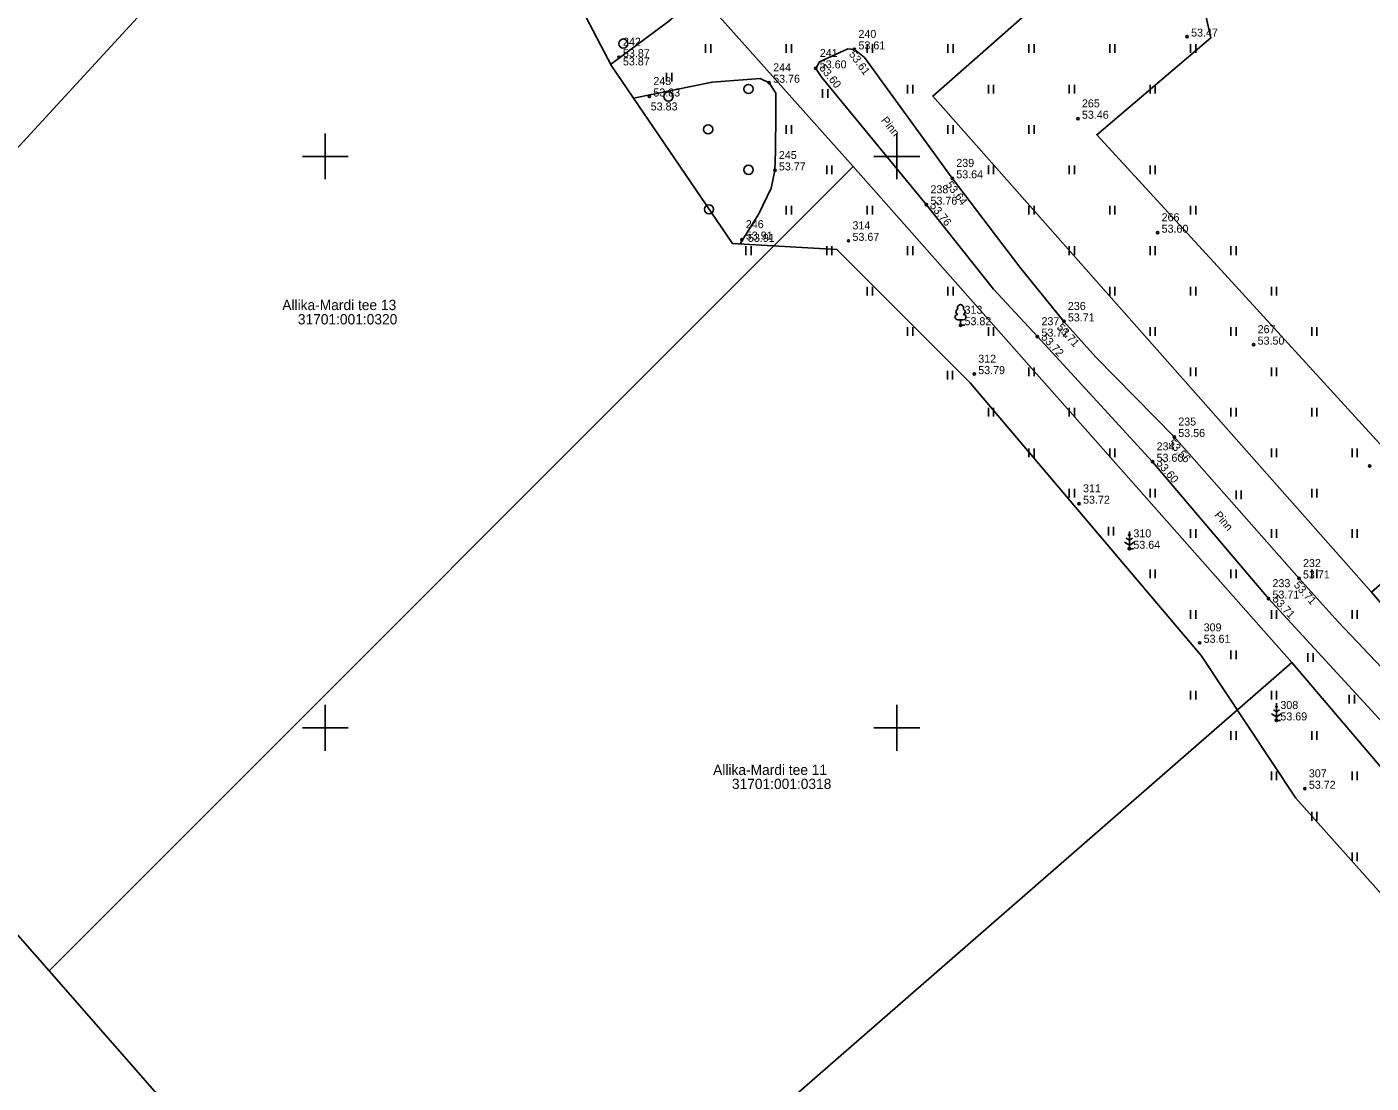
# Model space of a CAD drawing. Extents: x 538599 to 541973, y 6559689 to 6564516.
# Drawn here: x 540273.9 to 540391.5, y 6561418.9 to 6561511.3 of the extents above; entities that cross this region are included whole.
import ezdxf

# ---------------------------------------------------------------- set-up
doc = ezdxf.new("R2010")
doc.units = 0
for name, color, linetype in [('HALJASTUS', 7, 'Continuous'), ('KORGUS-EH2000', 7, 'Continuous'), ('MOOTKORG-EH2000', 7, 'Continuous'), ('MOOTMPUNKT', 7, 'Continuous'), ('MOOTNR', 7, 'Continuous'), ('MOOTPIIR', 7, 'Continuous'), ('PIIR', 7, 'Continuous'), ('PUU', 7, 'Continuous'), ('TEE', 7, 'Continuous'), ('VORK', 7, 'Continuous')]:
    doc.layers.add(name, color=color, linetype=linetype)

msp = doc.modelspace()

# ---------------------------------------------------------------- linework, layer by layer
at = {"layer": 'HALJASTUS'}
for p, q in [((540333.26, 6561509.81), (540333.26, 6561509.05)), ((540333.72, 6561509.81), (540333.72, 6561509.05)), ((540340.33, 6561509.81), (540340.33, 6561509.05)), ((540340.79, 6561509.81), (540340.79, 6561509.05)), ((540347.4, 6561509.81), (540347.4, 6561509.05)), ((540347.86, 6561509.81), (540347.86, 6561509.05)), ((540354.47, 6561509.81), (540354.47, 6561509.05)), ((540354.93, 6561509.81), (540354.93, 6561509.05)), ((540361.54, 6561509.81), (540361.54, 6561509.05)), ((540362, 6561509.81), (540362, 6561509.05)), ((540368.62, 6561509.81), (540368.62, 6561509.05)), ((540369.07, 6561509.81), (540369.07, 6561509.05)), ((540375.69, 6561509.81), (540375.69, 6561509.05)), ((540376.14, 6561509.81), (540376.14, 6561509.05)), ((540329.85, 6561507.31), (540329.85, 6561506.55)), ((540330.31, 6561507.31), (540330.31, 6561506.55)), ((540343.49, 6561505.87), (540343.49, 6561505.11)), ((540343.95, 6561505.87), (540343.95, 6561505.11)), ((540350.94, 6561506.27), (540350.94, 6561505.51)), ((540351.39, 6561506.27), (540351.39, 6561505.51)), ((540358.01, 6561506.27), (540358.01, 6561505.51)), ((540358.46, 6561506.27), (540358.46, 6561505.51)), ((540365.08, 6561506.27), (540365.08, 6561505.51)), ((540365.53, 6561506.27), (540365.53, 6561505.51)), ((540372.15, 6561506.27), (540372.15, 6561505.51)), ((540372.61, 6561506.27), (540372.61, 6561505.51)), ((540340.33, 6561502.74), (540340.33, 6561501.98)), ((540340.79, 6561502.74), (540340.79, 6561501.98)), ((540354.47, 6561502.74), (540354.47, 6561501.98)), ((540354.93, 6561502.74), (540354.93, 6561501.98)), ((540361.54, 6561502.74), (540361.54, 6561501.98)), ((540362, 6561502.74), (540362, 6561501.98)), ((540343.87, 6561499.2), (540343.87, 6561498.44)), ((540344.32, 6561499.2), (540344.32, 6561498.44)), ((540358.01, 6561499.2), (540358.01, 6561498.44)), ((540358.46, 6561499.2), (540358.46, 6561498.44)), ((540365.08, 6561499.2), (540365.08, 6561498.44)), ((540365.53, 6561499.2), (540365.53, 6561498.44)), ((540372.15, 6561499.2), (540372.15, 6561498.44)), ((540372.61, 6561499.2), (540372.61, 6561498.44)), ((540340.33, 6561495.67), (540340.33, 6561494.91)), ((540340.79, 6561495.67), (540340.79, 6561494.91)), ((540347.4, 6561495.67), (540347.4, 6561494.91)), ((540347.86, 6561495.67), (540347.86, 6561494.91)), ((540361.54, 6561495.67), (540361.54, 6561494.91)), ((540362, 6561495.67), (540362, 6561494.91)), ((540368.62, 6561495.67), (540368.62, 6561494.91)), ((540369.07, 6561495.67), (540369.07, 6561494.91)), ((540375.69, 6561495.67), (540375.69, 6561494.91)), ((540376.14, 6561495.67), (540376.14, 6561494.91)), ((540336.8, 6561492.13), (540336.8, 6561491.37)), ((540337.25, 6561492.13), (540337.25, 6561491.37)), ((540343.87, 6561492.13), (540343.87, 6561491.37)), ((540344.32, 6561492.13), (540344.32, 6561491.37)), ((540350.94, 6561492.13), (540350.94, 6561491.37)), ((540351.39, 6561492.13), (540351.39, 6561491.37)), ((540365.08, 6561492.13), (540365.08, 6561491.37)), ((540365.53, 6561492.13), (540365.53, 6561491.37)), ((540372.15, 6561492.13), (540372.15, 6561491.37)), ((540372.61, 6561492.13), (540372.61, 6561491.37)), ((540379.22, 6561492.13), (540379.22, 6561491.37)), ((540379.68, 6561492.13), (540379.68, 6561491.37)), ((540347.4, 6561488.6), (540347.4, 6561487.84)), ((540347.86, 6561488.6), (540347.86, 6561487.84)), ((540354.47, 6561488.6), (540354.47, 6561487.84)), ((540354.93, 6561488.6), (540354.93, 6561487.84)), ((540368.62, 6561488.6), (540368.62, 6561487.84)), ((540369.07, 6561488.6), (540369.07, 6561487.84)), ((540375.69, 6561488.6), (540375.69, 6561487.84)), ((540376.14, 6561488.6), (540376.14, 6561487.84)), ((540382.76, 6561488.6), (540382.76, 6561487.84)), ((540383.21, 6561488.6), (540383.21, 6561487.84)), ((540350.94, 6561485.06), (540350.94, 6561484.3)), ((540351.39, 6561485.06), (540351.39, 6561484.3)), ((540358.01, 6561485.06), (540358.01, 6561484.3)), ((540358.46, 6561485.06), (540358.46, 6561484.3)), ((540372.15, 6561485.06), (540372.15, 6561484.3)), ((540372.61, 6561485.06), (540372.61, 6561484.3)), ((540379.22, 6561485.06), (540379.22, 6561484.3)), ((540379.68, 6561485.06), (540379.68, 6561484.3)), ((540386.29, 6561485.06), (540386.29, 6561484.3)), ((540386.75, 6561485.06), (540386.75, 6561484.3)), ((540354.43, 6561481.25), (540354.43, 6561480.49)), ((540354.88, 6561481.25), (540354.88, 6561480.49)), ((540361.54, 6561481.53), (540361.54, 6561480.76)), ((540362, 6561481.53), (540362, 6561480.76)), ((540375.69, 6561481.53), (540375.69, 6561480.76)), ((540376.14, 6561481.53), (540376.14, 6561480.76)), ((540382.76, 6561481.53), (540382.76, 6561480.76)), ((540383.21, 6561481.53), (540383.21, 6561480.76)), ((540358.01, 6561477.99), (540358.01, 6561477.23)), ((540358.46, 6561477.99), (540358.46, 6561477.23)), ((540365.08, 6561477.99), (540365.08, 6561477.23)), ((540365.53, 6561477.99), (540365.53, 6561477.23)), ((540379.22, 6561477.99), (540379.22, 6561477.23)), ((540379.68, 6561477.99), (540379.68, 6561477.23)), ((540386.29, 6561477.99), (540386.29, 6561477.23)), ((540386.75, 6561477.99), (540386.75, 6561477.23)), ((540361.54, 6561474.45), (540361.54, 6561473.69)), ((540362, 6561474.45), (540362, 6561473.69)), ((540368.62, 6561474.45), (540368.62, 6561473.69)), ((540369.07, 6561474.45), (540369.07, 6561473.69)), ((540382.76, 6561474.45), (540382.76, 6561473.69)), ((540383.21, 6561474.45), (540383.21, 6561473.69)), ((540389.83, 6561474.45), (540389.83, 6561473.69)), ((540390.28, 6561474.45), (540390.28, 6561473.69)), ((540365.08, 6561470.92), (540365.08, 6561470.16)), ((540365.53, 6561470.92), (540365.53, 6561470.16)), ((540372.15, 6561470.92), (540372.15, 6561470.16)), ((540372.61, 6561470.92), (540372.61, 6561470.16)), ((540379.67, 6561470.77), (540379.67, 6561470.01)), ((540380.13, 6561470.77), (540380.13, 6561470.01)), ((540386.29, 6561470.92), (540386.29, 6561470.16)), ((540386.75, 6561470.92), (540386.75, 6561470.16)), ((540368.51, 6561467.6), (540368.51, 6561466.84)), ((540368.96, 6561467.6), (540368.96, 6561466.84)), ((540375.69, 6561467.38), (540375.69, 6561466.62)), ((540376.14, 6561467.38), (540376.14, 6561466.62)), ((540382.76, 6561467.38), (540382.76, 6561466.62)), ((540383.21, 6561467.38), (540383.21, 6561466.62)), ((540389.83, 6561467.38), (540389.83, 6561466.62)), ((540390.28, 6561467.38), (540390.28, 6561466.62)), ((540372.15, 6561463.85), (540372.15, 6561463.09)), ((540372.61, 6561463.85), (540372.61, 6561463.09)), ((540379.22, 6561463.85), (540379.22, 6561463.09)), ((540379.68, 6561463.85), (540379.68, 6561463.09)), ((540386.29, 6561463.85), (540386.29, 6561463.09)), ((540386.75, 6561463.85), (540386.75, 6561463.09)), ((540375.69, 6561460.31), (540375.69, 6561459.55)), ((540376.14, 6561460.31), (540376.14, 6561459.55)), ((540382.76, 6561460.31), (540382.76, 6561459.55)), ((540383.21, 6561460.31), (540383.21, 6561459.55)), ((540389.83, 6561460.31), (540389.83, 6561459.55)), ((540390.28, 6561460.31), (540390.28, 6561459.55)), ((540379.22, 6561456.78), (540379.22, 6561456.02)), ((540379.68, 6561456.78), (540379.68, 6561456.02)), ((540385.96, 6561456.54), (540385.96, 6561455.78)), ((540386.41, 6561456.54), (540386.41, 6561455.78)), ((540375.69, 6561453.24), (540375.69, 6561452.48)), ((540376.14, 6561453.24), (540376.14, 6561452.48)), ((540382.76, 6561453.24), (540382.76, 6561452.48)), ((540383.21, 6561453.24), (540383.21, 6561452.48)), ((540389.56, 6561452.89), (540389.56, 6561452.13)), ((540390.02, 6561452.89), (540390.02, 6561452.13)), ((540379.22, 6561449.71), (540379.22, 6561448.94)), ((540379.68, 6561449.71), (540379.68, 6561448.94)), ((540386.29, 6561449.71), (540386.29, 6561448.94)), ((540386.75, 6561449.71), (540386.75, 6561448.94)), ((540382.76, 6561446.17), (540382.76, 6561445.41)), ((540383.21, 6561446.17), (540383.21, 6561445.41)), ((540389.83, 6561446.17), (540389.83, 6561445.41)), ((540390.28, 6561446.17), (540390.28, 6561445.41)), ((540386.29, 6561442.64), (540386.29, 6561441.87)), ((540386.75, 6561442.64), (540386.75, 6561441.87)), ((540389.83, 6561439.1), (540389.83, 6561438.34)), ((540390.28, 6561439.1), (540390.28, 6561438.34))]:
    msp.add_line(p, q, dxfattribs=at)
for points in [[(540324.94, 6561508.04), (540330.06, 6561511.84), (540332.61, 6561514.07), (540334.35, 6561516.07), (540335.39, 6561517.77), (540337.56, 6561524), (540339.56, 6561527.11), (540341.47, 6561528.6), (540348.13, 6561532.08), (540349.71, 6561533.01), (540357.68, 6561539.9)], [(540326.96, 6561505.08), (540333.83, 6561506.5), (540338.04, 6561506.82), (540338.83, 6561506.44), (540339.41, 6561505.53), (540339.42, 6561503.82), (540339.37, 6561500.46), (540339.33, 6561498.77), (540339, 6561497.21), (540337.94, 6561494.97), (540336.26, 6561492.33)]]:
    msp.add_lwpolyline(points, dxfattribs=at)
for centre in [(540326.07, 6561509.87), (540337.02, 6561505.89), (540330.02, 6561505.24), (540333.49, 6561502.36), (540337.02, 6561498.82), (540333.57, 6561495.37)]:
    msp.add_circle(centre, 0.4, dxfattribs=at)
at = {"layer": 'KORGUS-EH2000'}
for centre in [(540375.39, 6561510.48), (540325.69, 6561508.68), (540346.29, 6561509.36), (540342.91, 6561507.7), (540338.83, 6561506.44), (540328.35, 6561505.24), (540365.84, 6561503.29), (540354.85, 6561498.08), (540352.59, 6561495.77), (540372.81, 6561493.32), (540336.44, 6561492.72), (540345.77, 6561492.61), (540364.61, 6561485.56), (540362.3, 6561484.23), (540381.21, 6561483.53), (540356.77, 6561480.95), (540374.27, 6561475.45), (540372.37, 6561473.28), (540391.36, 6561472.92), (540365.94, 6561469.61), (540385.18, 6561463.07), (540382.51, 6561461.31), (540376.49, 6561457.44), (540385.69, 6561444.67)]:
    msp.add_circle(centre, 0.1, dxfattribs=at)
at = {"layer": 'MOOTMPUNKT'}
for centre in [(540375.39, 6561510.48), (540325.69, 6561508.68), (540346.29, 6561509.36), (540342.91, 6561507.7), (540338.83, 6561506.44), (540328.35, 6561505.24), (540365.84, 6561503.29), (540339.33, 6561498.77), (540354.85, 6561498.08), (540352.59, 6561495.77), (540372.81, 6561493.32), (540336.44, 6561492.72), (540345.77, 6561492.61), (540355.57, 6561485.23), (540364.61, 6561485.56), (540362.3, 6561484.23), (540381.21, 6561483.53), (540356.77, 6561480.95), (540374.27, 6561475.45), (540372.37, 6561473.28), (540391.36, 6561472.92), (540365.94, 6561469.61), (540370.34, 6561465.67), (540385.18, 6561463.07), (540382.51, 6561461.31), (540376.49, 6561457.44), (540383.2, 6561450.65), (540385.69, 6561444.67)]:
    msp.add_circle(centre, 0.1, dxfattribs=at)
at = {"layer": 'MOOTPIIR'}
msp.add_lwpolyline([(540393.81, 6561473.15), (540378.36, 6561490.03), (540367.49, 6561501.89), (540377.47, 6561510.36), (540374.29, 6561524.39), (540363.85, 6561533.7), (540344.56, 6561553.05), (540315.14, 6561526.81), (540325.03, 6561507.91), (540335.62, 6561492.37), (540344.75, 6561491.86), (540356.42, 6561480.19), (540366.31, 6561468.52), (540376.63, 6561456.34), (540384.89, 6561443.84), (540403.97, 6561422.47)], dxfattribs=at)
at = {"layer": 'PIIR'}
msp.add_lwpolyline([(540274.62, 6561658.98), (540308.95, 6561626.96), (540342.1, 6561660.8), (540380.29, 6561616.49), (540315.96, 6561547.42), (540242.15, 6561467.11), (540086.59, 6561298.21), (539860.44, 6561301.54), (539867.53, 6561320.47), (539886.51, 6561388.42), (539892.89, 6561422.22), (539899.82, 6561444.13), (539930.12, 6561502.67), (539948.68, 6561538.36), (539974.66, 6561584.65), (539991.12, 6561609.35), (540012.97, 6561633.62), (540053.54, 6561681.61)], dxfattribs=at)
for points in [[(540353.14, 6561505.27), (540364.11, 6561514.94), (540423.13, 6561566.69), (540460.86, 6561522.64), (540391.51, 6561461.86)], [(540242.15, 6561467.11), (540315.96, 6561547.42), (540337.36, 6561523.32), (540330.12, 6561517.14), (540346.17, 6561499.11), (540275.86, 6561428.73)], [(540491.21, 6561183.5), (540566.07, 6561233.36), (540528.84, 6561281.85), (540494.34, 6561324.62), (540458.27, 6561368.69), (540424.68, 6561408.57), (540384.55, 6561455.73), (540346.17, 6561499.11), (540330.12, 6561517.14), (540337.36, 6561523.32), (540348.28, 6561532.96), (540364.11, 6561514.94), (540353.14, 6561505.27), (540391.51, 6561461.86), (540431.74, 6561414.74), (540465.17, 6561374.89), (540501.31, 6561330.86), (540535.92, 6561287.97), (540573.77, 6561238.75), (540640.63, 6561283.66), (540646.74, 6561272.89), (540499, 6561174.36)], [(540275.86, 6561428.73), (540346.17, 6561499.11), (540384.55, 6561455.73), (540309.49, 6561390.29)], [(540086.59, 6561298.21), (540242.15, 6561467.11), (540275.86, 6561428.73), (540309.49, 6561390.29), (540350.66, 6561343.77), (540384.73, 6561304.57), (540422.29, 6561261.69), (540458.8, 6561220.37), (540491.21, 6561183.5), (540499, 6561174.36), (540490.55, 6561169.03), (539847.51, 6560731.53), (539695.32, 6560914.32), (539729.44, 6560945.74), (539769.27, 6560982.22), (539923.85, 6561123.78), (539979.73, 6561200.97), (540031.35, 6561186.14), (540104.75, 6561275.5)], [(540309.49, 6561390.29), (540384.55, 6561455.73), (540424.68, 6561408.57), (540350.66, 6561343.77)]]:
    msp.add_lwpolyline(points, close=True, dxfattribs=at)
at = {"layer": 'PUU'}
for p, q in [((540355.81, 6561485.71), (540355.33, 6561485.71)), ((540355.57, 6561485.23), (540355.57, 6561485.71)), ((540355.95, 6561485.23), (540355.57, 6561485.23)), ((540370.34, 6561466.42), (540370.07, 6561466.6)), ((540370.34, 6561466.82), (540370.21, 6561466.91)), ((540370.34, 6561467.17), (540370.34, 6561465.67)), ((540370.46, 6561466.91), (540370.34, 6561466.82)), ((540370.6, 6561466.6), (540370.34, 6561466.42)), ((540369.91, 6561466.26), (540370.34, 6561465.98)), ((540370.34, 6561465.98), (540370.76, 6561466.26)), ((540370.7, 6561465.67), (540370.34, 6561465.67)), ((540382.78, 6561451.24), (540383.2, 6561450.96)), ((540383.2, 6561451.4), (540382.94, 6561451.58)), ((540383.2, 6561451.8), (540383.08, 6561451.88)), ((540383.2, 6561452.15), (540383.2, 6561450.65)), ((540383.33, 6561451.88), (540383.2, 6561451.8)), ((540383.47, 6561451.58), (540383.2, 6561451.4)), ((540383.2, 6561450.96), (540383.63, 6561451.24)), ((540383.56, 6561450.65), (540383.2, 6561450.65))]:
    msp.add_line(p, q, dxfattribs=at)
for centre, radius, start, end in [((540355.4, 6561486.4), 0.233, 109.0217, 253.1415), ((540355.57, 6561486.75), 0.277, 332.5799, 207.4201), ((540355.74, 6561486.4), 0.233, 286.8508, 70.9859), ((540355.33, 6561485.94), 0.238, 90.0016, 269.3953), ((540355.81, 6561485.94), 0.238, 270.6047, 89.9984)]:
    msp.add_arc(centre, radius, start, end, dxfattribs=at)
at = {"layer": 'TEE'}
msp.add_lwpolyline([(540392.51, 6561450.44), (540382.51, 6561461.31), (540372.37, 6561473.28), (540362.3, 6561484.23), (540358.45, 6561488.39), (540352.59, 6561495.77), (540343.44, 6561506.9), (540342.91, 6561507.7), (540343.24, 6561508.26), (540345.71, 6561509.42), (540346.29, 6561509.36), (540347.18, 6561508.65), (540354.85, 6561498.08), (540360.77, 6561490.31), (540364.61, 6561485.56), (540367.42, 6561482.43), (540374.27, 6561475.45), (540385.18, 6561463.07), (540388.6, 6561459.28), (540394.61, 6561452.94)], dxfattribs=at)
at = {"layer": 'VORK'}
for p, q in [((540300, 6561502), (540300, 6561498)), ((540350, 6561502), (540350, 6561498)), ((540298, 6561500), (540302, 6561500)), ((540348, 6561500), (540352, 6561500)), ((540300, 6561452), (540300, 6561448)), ((540350, 6561452), (540350, 6561448)), ((540298, 6561450), (540302, 6561450)), ((540348, 6561450), (540352, 6561450))]:
    msp.add_line(p, q, dxfattribs=at)

# ---------------------------------------------------------------- texts
at = {"layer": 'KORGUS-EH2000'}
for s, p in [('53.47', (540375.74, 6561510.48)), ('53.87', (540326.04, 6561507.96)), ('53.76', (540339.18, 6561506.44)), ('53.83', (540328.47, 6561504.02)), ('53.46', (540366.19, 6561503.29)), ('53.60', (540373.16, 6561493.32)), ('53.91', (540336.97, 6561492.52)), ('53.67', (540346.12, 6561492.61)), ('53.50', (540381.56, 6561483.53)), ('53.79', (540357.12, 6561480.95)), ('53.72', (540366.29, 6561469.61)), ('53.61', (540376.84, 6561457.44)), ('53.72', (540386.04, 6561444.67))]:
    msp.add_text(s, height=0.7, dxfattribs=at).set_placement(p)
for s, rotation, p in [('53.61', 305.9623, (540345.77, 6561508.93)), ('53.60', 309.4225, (540343.17, 6561507.7)), ('53.64', 307.3237, (540354.24, 6561497.51)), ('53.76', 308.4943, (540352.84, 6561495.66)), ('53.71', 311.956, (540363.95, 6561485)), ('53.72', 312.606, (540362.58, 6561484.13)), ('53.56', 311.4044, (540373.7, 6561474.89)), ('53.60', 310.2705, (540372.66, 6561473.13)), ('53.71', 312.0619, (540384.68, 6561462.45)), ('53.71', 312.5962, (540382.8, 6561461.22))]:
    msp.add_text(s, height=0.7, rotation=rotation, dxfattribs=at).set_placement(p)
at = {"layer": 'MOOTKORG-EH2000'}
for s, p in [('53.47', (540375.74, 6561510.48)), ('53.61', (540346.64, 6561509.36)), ('53.87', (540326.04, 6561508.68)), ('53.60', (540343.26, 6561507.7)), ('53.76', (540339.18, 6561506.44)), ('53.83', (540328.7, 6561505.24)), ('53.46', (540366.19, 6561503.29)), ('53.77', (540339.68, 6561498.77)), ('53.64', (540355.2, 6561498.08)), ('53.76', (540352.94, 6561495.77)), ('53.91', (540336.79, 6561492.72)), ('53.60', (540373.16, 6561493.32)), ('53.67', (540346.12, 6561492.61)), ('53.82', (540355.92, 6561485.23)), ('53.71', (540364.96, 6561485.56)), ('53.72', (540362.65, 6561484.23)), ('53.50', (540381.56, 6561483.53)), ('53.79', (540357.12, 6561480.95)), ('53.56', (540374.62, 6561475.45)), ('53.60', (540372.72, 6561473.28)), ('53.72', (540366.29, 6561469.61)), ('53.64', (540370.69, 6561465.67)), ('53.71', (540385.53, 6561463.07)), ('53.71', (540382.86, 6561461.31)), ('53.61', (540376.84, 6561457.44)), ('53.69', (540383.55, 6561450.65)), ('53.72', (540386.04, 6561444.67))]:
    msp.add_text(s, height=0.7, dxfattribs=at).set_placement(p)
at = {"layer": 'MOOTNR'}
for s, p in [('240', (540346.64, 6561510.36)), ('242', (540326.04, 6561509.68)), ('241', (540343.26, 6561508.7)), ('244', (540339.18, 6561507.44)), ('243', (540328.7, 6561506.24)), ('265', (540366.19, 6561504.29)), ('245', (540339.68, 6561499.77)), ('239', (540355.2, 6561499.08)), ('238', (540352.94, 6561496.77)), ('266', (540373.16, 6561494.32)), ('246', (540336.79, 6561493.72)), ('314', (540346.12, 6561493.61)), ('313', (540355.92, 6561486.23)), ('236', (540364.96, 6561486.56)), ('237', (540362.65, 6561485.23)), ('267', (540381.56, 6561484.53)), ('312', (540357.12, 6561481.95)), ('235', (540374.62, 6561476.45)), ('234', (540372.72, 6561474.28)), ('311', (540366.29, 6561470.61)), ('310', (540370.69, 6561466.67)), ('232', (540385.53, 6561464.07)), ('233', (540382.86, 6561462.31)), ('309', (540376.84, 6561458.44)), ('308', (540383.55, 6561451.65)), ('307', (540386.04, 6561445.67))]:
    msp.add_text(s, height=0.7, dxfattribs=at).set_placement(p)
at = {"layer": 'PIIR'}
for s, rotation, p in [('Allika-Mardi tee 13', 360, (540296.24, 6561486.55)), ('31701:001:0320', 360, (540297.6, 6561485.3)), ('Allika-Mardi tee 11', 0, (540333.93, 6561445.88)), ('31701:001:0318', 0, (540335.57, 6561444.65))]:
    msp.add_text(s, height=0.9, rotation=rotation, dxfattribs=at).set_placement(p)
at = {"layer": 'TEE'}
for rotation, p in [(309.0483, (540348.58, 6561503.13)), (310.2705, (540377.73, 6561468.59))]:
    msp.add_text('Pinn', height=0.7, rotation=rotation, dxfattribs=at).set_placement(p)

doc.saveas('drawing.dxf')
